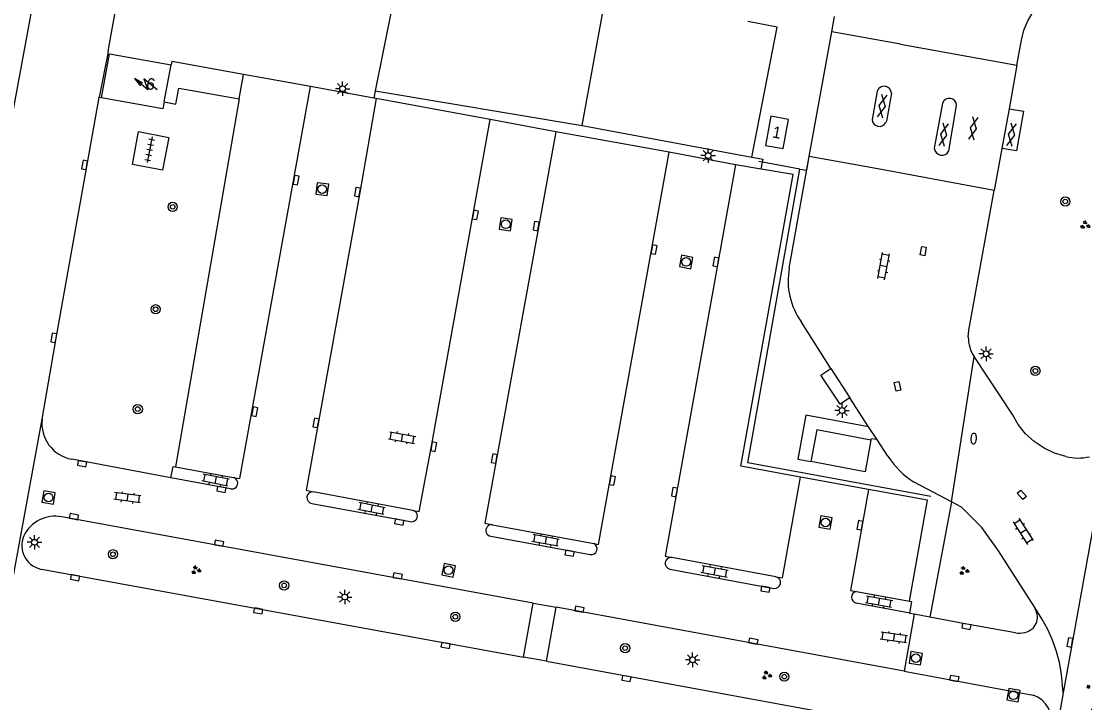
# Model space of a CAD drawing. Extents: x 130998 to 133001, y 398999 to 403002.
# Drawn here: x 132109.2 to 132201.3, y 399492.3 to 399551.3 of the extents above; entities that cross this region are included whole.
import ezdxf

# ---------------------------------------------------------------- set-up
doc = ezdxf.new("R2010")
doc.units = 0
for name, color, linetype in [('gg-afsc-erfafscheiding', 7, 'Continuous'), ('gg-afsc-hekwerk', 7, 'Continuous'), ('gg-anno-huisnummerreeks BGT', 7, 'Continuous'), ('gg-anno-openbare ruimte label', 7, 'Continuous'), ('gg-bbg-bijgebouw', 7, 'Continuous'), ('gg-bbg-hoofdgebouw', 7, 'Continuous'), ('gg-knt-verharding', 7, 'Continuous'), ('gg-knt-verharding nz', 7, 'Continuous'), ('gt-grn-groengrens', 7, 'Continuous'), ('gt-grn-vlakafsluiter', 7, 'Continuous'), ('gt-grn-weggrens', 7, 'Continuous'), ('gt-symb-boom', 7, 'Continuous'), ('gt-symb-brandkraan', 7, 'Continuous'), ('gt-symb-gesloten verharding', 7, 'Continuous'), ('gt-symb-groenvak', 7, 'Continuous'), ('gt-symb-klinker verharding', 7, 'Continuous'), ('gt-symb-kolk', 7, 'Continuous'), ('gt-symb-kolk center center', 7, 'Continuous'), ('gt-symb-lichtmast', 7, 'Continuous'), ('gt-symb-rioolschacht', 7, 'Continuous'), ('gt-symb-tegel verharding', 7, 'Continuous'), ('gt-symb-trafo symbool', 7, 'Continuous')]:
    doc.layers.add(name, color=color, linetype=linetype)

# ---------------------------------------------------------------- blocks, each defined once
blk = doc.blocks.new('gt0-BOOM')
at = {"layer": 'gt-symb-boom'}
for radius in [0.4, 0.2]:
    blk.add_circle((0, 0), radius, dxfattribs=at)
blk = doc.blocks.new('gt0-KOLK')
at = {"layer": 'gt-symb-kolk'}
blk.add_lwpolyline([(0, 0), (0.375, 0), (0.375, 0.4), (-0.375, 0.4), (-0.375, 0), (0, 0)], dxfattribs=at)
blk = doc.blocks.new('gt0-GRVAK')
at = {"layer": 'gt-symb-groenvak'}
for p, q in [((-0.11, 0.189), (-0.228, 0.24)), ((-0.182, 0.153), (0.088, 0.153)), ((-0.091, 0.211), (-0.156, 0.322)), ((-0.047, 0.214), (-0.047, 0.393)), ((-0.004, 0.211), (0.061, 0.322)), ((0.015, 0.189), (0.133, 0.24)), ((0.262, -0.052), (0.197, 0.059)), ((0.305, -0.049), (0.305, 0.13)), ((0.349, -0.052), (0.414, 0.059)), ((-0.245, -0.228), (-0.363, -0.177)), ((-0.318, -0.264), (-0.047, -0.264)), ((-0.226, -0.206), (-0.291, -0.095)), ((-0.183, -0.203), (-0.183, -0.024)), ((-0.139, -0.206), (-0.074, -0.095)), ((-0.12, -0.228), (-0.002, -0.177)), ((0.243, -0.074), (0.125, -0.023)), ((0.17, -0.11), (0.441, -0.11)), ((0.368, -0.074), (0.486, -0.023))]:
    blk.add_line(p, q, dxfattribs=at)
blk = doc.blocks.new('gt0-LMAST')
at = {"layer": 'gt-symb-lichtmast'}
for p, q in [((-0.182, 0.173), (-0.447, 0.438)), ((-0.005, 0.246), (-0.005, 0.621)), ((0.172, 0.173), (0.437, 0.438)), ((-0.255, -0.004), (-0.63, -0.004)), ((-0.182, -0.181), (-0.447, -0.446)), ((-0.005, -0.254), (-0.005, -0.629)), ((0.437, -0.446), (0.172, -0.181)), ((0.245, -0.004), (0.62, -0.004))]:
    blk.add_line(p, q, dxfattribs=at)
blk.add_circle((-0.005, -0.004), 0.25, dxfattribs=at)
blk = doc.blocks.new('gt0-RS')
at = {"layer": 'gt-symb-rioolschacht'}
blk.add_lwpolyline([(-0.5, -0.5), (0.5, -0.5), (0.5, 0.5), (-0.5, 0.5)], close=True, dxfattribs=at)
blk.add_circle((0, 0), 0.375, dxfattribs=at)
blk = doc.blocks.new('gt0-GESVH1')
at = {"layer": 'gt-symb-gesloten verharding'}
for p, q in [((-0.992, -0.261), (0.008, 0.239)), ((0.008, -0.261), (-0.992, 0.239)), ((0.008, 0.239), (1.008, -0.261)), ((1.008, 0.239), (0.008, -0.261))]:
    blk.add_line(p, q, dxfattribs=at)
blk = doc.blocks.new('gt0-TEG1')
at = {"layer": 'gt-symb-tegel verharding'}
for p, q in [((-1.125, 0), (1.125, 0)), ((-0.9, -0.25), (-0.9, 0.25)), ((-0.45, -0.25), (-0.45, 0.25)), ((0, -0.25), (0, 0.25)), ((0.45, -0.25), (0.45, 0.25)), ((0.9, -0.25), (0.9, 0.25))]:
    blk.add_line(p, q, dxfattribs=at)
blk = doc.blocks.new('gt0-HSP')
at = {"layer": 'gt-symb-trafo symbool'}
for points in [[(0.771, 0.746), (-0.529, -0.004), (0.471, -0.004), (-0.829, -0.754)], [(-0.217, -0.24), (-0.829, -0.754), (-0.077, -0.48)]]:
    blk.add_lwpolyline(points, dxfattribs=at)
blk = doc.blocks.new('gt0-KL1')
at = {"layer": 'gt-symb-klinker verharding'}
for p, q in [((-1.15, 0.3), (1.15, 0.3)), ((-1, -0.3), (-1, 0.3)), ((-0.5, 0.3), (-0.5, 0.45)), ((0, -0.3), (0, 0.3)), ((0.5, 0.3), (0.5, 0.45)), ((1, -0.3), (1, 0.3)), ((-1.15, -0.3), (1.15, -0.3)), ((-0.5, -0.45), (-0.5, -0.3)), ((0.5, -0.45), (0.5, -0.3))]:
    blk.add_line(p, q, dxfattribs=at)
blk = doc.blocks.new('gt0-KOLKCC')
at = {"layer": 'gt-symb-kolk center center'}
blk.add_lwpolyline([(-0.375, 0.2), (0.375, 0.2), (0.375, -0.2), (-0.375, -0.2)], close=True, dxfattribs=at)
blk = doc.blocks.new('gt0-BR')
at = {"layer": 'gt-symb-brandkraan'}
for centre, radius, start, end in [((-0.244, 0), 0.206, 107.56694, 252.43307), ((0.599, -2.664), 3, 106.89205, 107.56694), ((0, -0.691), 0.938, 73.10799, 106.89205), ((-0.599, -2.664), 3, 72.43309, 73.10799), ((0.244, 0), 0.206, 287.56695, 72.43309), ((0.599, 2.664), 3, 252.43307, 253.10797), ((0, 0.691), 0.938, 253.10797, 286.89206), ((-0.599, 2.664), 3, 286.89206, 287.56695)]:
    blk.add_arc(centre, radius, start, end, dxfattribs=at)

msp = doc.modelspace()

# ---------------------------------------------------------------- linework, layer by layer
at = {"layer": 'gg-afsc-erfafscheiding'}
msp.add_line((132157.773, 399542.297), (132172.48, 399539.565), dxfattribs=at)
msp.add_lwpolyline([(132172.48, 399539.565), (132174.679, 399550.803), (132172.135, 399551.301)], dxfattribs=at)
at = {"layer": 'gg-afsc-hekwerk'}
for p, q in [((132122.24, 399547.841), (132122.188, 399547.553)), ((132128.45, 399546.723), (132122.24, 399547.841)), ((132134.249, 399545.665), (132128.45, 399546.723)), ((132139.741, 399544.671), (132134.249, 399545.665)), ((132139.867, 399545.301), (132139.741, 399544.671)), ((132173.4, 399539.131), (132173.082, 399539.19)), ((132176.622, 399538.532), (132173.4, 399539.131))]:
    msp.add_line(p, q, dxfattribs=at)
msp.add_lwpolyline([(132187.97, 399510.197), (132172.118, 399513.098), (132176.622, 399538.532)], dxfattribs=at)
at = {"layer": 'gg-bbg-bijgebouw'}
for points in [[(132182.784, 399515.073), (132178.09, 399515.95), (132177.582, 399513.21)], [(132182.784, 399515.073), (132182.276, 399512.333), (132177.582, 399513.21)]]:
    msp.add_lwpolyline(points, dxfattribs=at)
at = {"layer": 'gg-bbg-hoofdgebouw'}
for p, q in [((132157.773, 399542.297), (132161.616, 399563.471)), ((132121.583, 399544.34), (132122.188, 399547.553)), ((132139.867, 399545.301), (132157.773, 399542.297)), ((132174.123, 399543.098), (132173.664, 399540.58))]:
    msp.add_line(p, q, dxfattribs=at)
for points in [[(132133.567, 399568.656), (132131.765, 399558.5), (132142.135, 399556.65), (132139.867, 399545.301)], [(132116.165, 399544.687), (132116.839, 399548.498), (132122.188, 399547.553)], [(132121.583, 399544.34), (132121.472, 399543.748), (132116.165, 399544.687)], [(132173.664, 399540.58), (132175.189, 399540.302), (132175.648, 399542.82), (132174.123, 399543.098)]]:
    msp.add_lwpolyline(points, dxfattribs=at)
at = {"layer": 'gg-knt-verharding'}
for p, q in [((132179.385, 399550.411), (132179.623, 399551.731)), ((132177.438, 399539.617), (132179.385, 399550.411)), ((132185.344, 399549.338), (132179.385, 399550.411)), ((132116.726, 399548.675), (132116.781, 399549.04)), ((132185.344, 399549.338), (132195.427, 399547.523)), ((132116.726, 399548.675), (132115.958, 399544.762)), ((132195.427, 399547.523), (132194.742, 399543.755)), ((132128.071, 399544.604), (132128.45, 399546.723)), ((132122.583, 399544.152), (132122.845, 399545.53)), ((132122.845, 399545.53), (132128.071, 399544.604)), ((132183.325, 399545.276), (132182.882, 399542.829)), ((132115.951, 399544.725), (132115.958, 399544.762)), ((132116.165, 399544.687), (132115.951, 399544.725)), ((132121.583, 399544.34), (132122.583, 399544.152)), ((132128.071, 399544.604), (132122.552, 399512.766)), ((132139.938, 399544.634), (132139.741, 399544.671)), ((132149.823, 399542.817), (132139.938, 399544.634)), ((132188.991, 399544.245), (132188.268, 399540.347)), ((132189.529, 399540.113), (132190.209, 399544.041)), ((132194.742, 399543.755), (132194.116, 399540.307)), ((132155.484, 399541.757), (132149.823, 399542.817)), ((132165.303, 399539.995), (132155.484, 399541.757)), ((132171.062, 399538.902), (132165.303, 399539.995)), ((132175.715, 399529.957), (132177.438, 399539.617)), ((132177.222, 399538.421), (132177.438, 399539.617)), ((132183.377, 399538.548), (132177.438, 399539.617)), ((132194.116, 399540.307), (132193.457, 399536.682)), ((132173.29, 399538.529), (132171.062, 399538.902)), ((132193.457, 399536.682), (132183.377, 399538.548)), ((132179.32, 399521.257), (132176.774, 399525.291)), ((132179.32, 399521.257), (132180.963, 399518.727)), ((132182.582, 399516.234), (132180.963, 399518.727)), ((132183.29, 399515.154), (132182.582, 399516.234)), ((132184.251, 399513.686), (132183.29, 399515.154)), ((132122.167, 399511.821), (132113.574, 399513.423)), ((132122.552, 399512.766), (132127.562, 399511.84)), ((132127.328, 399510.864), (132122.167, 399511.821)), ((132182.586, 399510.798), (132176.689, 399511.873)), ((132189.749, 399509.728), (132186.527, 399511.432)), ((132143.122, 399508.992), (132134.482, 399510.605)), ((132134.376, 399509.594), (132142.89, 399508.029)), ((132153.546, 399500.953), (132112.708, 399508.433)), ((132150.027, 399507.75), (132158.785, 399506.119)), ((132149.862, 399506.76), (132158.463, 399505.176)), ((132174.563, 399503.248), (132165.555, 399504.905)), ((132111.131, 399503.868), (132152.698, 399496.294)), ((132165.379, 399503.915), (132174.372, 399502.244)), ((132181.532, 399501.978), (132186.119, 399501.146)), ((132152.698, 399496.294), (132153.546, 399500.953)), ((132186.152, 399500.106), (132181.509, 399500.973)), ((132186.119, 399501.146), (132186.331, 399501.101)), ((132186.152, 399500.106), (132186.331, 399501.101)), ((132154.695, 399495.929), (132155.538, 399500.602)), ((132185.654, 399495.063), (132155.538, 399500.602)), ((132187.89, 399499.744), (132186.525, 399500)), ((132197.183, 399500), (132196.971, 399500.576)), ((132154.695, 399495.929), (132184.833, 399490.409)), ((132185.654, 399495.063), (132196.832, 399493.007))]:
    msp.add_line(p, q, dxfattribs=at)
for points in [[(132116.781, 399549.04), (132125.861, 399599.262), (132126.153, 399600.397), (132126.59, 399601.485), (132127.164, 399602.507), (132127.409, 399602.833)], [(132195.427, 399547.523), (132195.821, 399549.693), (132196.033, 399550.552), (132196.371, 399551.37), (132196.829, 399552.127), (132197.396, 399552.806), (132198.053, 399553.403), (132198.78, 399553.914)], [(132184.57, 399545.094), (132184.128, 399542.669), (132184.067, 399542.555)], [(132111.016, 399516.89), (132112.216, 399523.893), (132115.951, 399544.725)], [(132194.742, 399543.755), (132196.007, 399543.533), (132195.38, 399540.103), (132194.116, 399540.307)], [(132118.832, 399538.921), (132119.355, 399541.777), (132121.996, 399541.255), (132121.437, 399538.42), (132118.832, 399538.921)], [(132176.689, 399511.873), (132171.527, 399512.815), (132176.045, 399538.067), (132173.29, 399538.529)], [(132191.209, 399523.99), (132191.261, 399524.591), (132193.457, 399536.682)], [(132199.667, 399513.647), (132198.695, 399513.95), (132197.772, 399514.38), (132196.924, 399514.938), (132196.174, 399515.623), (132195.542, 399516.417), (132195.041, 399517.3), (132191.721, 399522.301)], [(132180.963, 399518.727), (132180.125, 399518.182), (132178.436, 399520.683), (132179.32, 399521.257)], [(132182.582, 399516.234), (132177.161, 399517.243), (132176.448, 399513.422), (132177.582, 399513.21)], [(132182.784, 399515.073), (132182.834, 399515.219), (132183.29, 399515.154)], [(132122.167, 399511.821), (132122.362, 399512.801), (132122.552, 399512.766)], [(132186.119, 399501.146), (132187.682, 399509.874), (132182.586, 399510.798)], [(132196.971, 399500.576), (132193.841, 399505.48), (132192.391, 399507.501), (132190.641, 399509.26), (132189.749, 399509.728)], [(132186.525, 399500), (132186.146, 399500.071), (132186.152, 399500.106)], [(132195.308, 399498.402), (132191.089, 399499.144), (132187.89, 399499.744)]]:
    msp.add_lwpolyline(points, dxfattribs=at)
for centre, radius, start, end in [((132183.928, 399545.055), 0.643, 3.4786, 159.88768), ((132189.579, 399544.02), 0.63, 1.95134, 159.03248), ((132183.511, 399542.85), 0.629, 181.92917, 332.03216), ((132188.928, 399540.389), 0.661, 183.66038, 335.31437), ((132181.668, 399528.855), 6.054, 169.51225, 216.06231), ((132194.376, 399524.028), 3.167, 180.68478, 213.04332), ((132114.127, 399516.508), 3.134, 173.00034, 259.84049), ((132190.559, 399517.78), 7.52, 212.98191, 237.5746), ((132200.718, 399518.07), 4.546, 256.63325, 282.46448), ((132127.451, 399511.351), 0.502, 255.82896, 77.20622), ((132134.449, 399510.097), 0.509, 86.27354, 261.75565), ((132112.146, 399505.473), 3.012, 79.2464, 154.23306), ((132143.015, 399508.508), 0.495, 255.44013, 77.46941), ((132149.938, 399507.256), 0.502, 79.83737, 261.23798), ((132111.35, 399505.947), 2.091, 156.4472, 263.99477), ((132158.562, 399505.669), 0.503, 258.69477, 63.59891), ((132165.469, 399504.41), 0.503, 80.14423, 259.69457), ((132174.449, 399502.75), 0.511, 261.37927, 77.07835), ((132181.614, 399501.473), 0.511, 99.24644, 258.13152), ((132195.761, 399499.761), 1.442, 317.60852, 9.54069), ((132195.65, 399500.231), 1.86, 259.4024, 309.20233), ((132196.05, 399490.766), 2.374, 345.10972, 70.76789)]:
    msp.add_arc(centre, radius, start, end, dxfattribs=at)
at = {"layer": 'gg-knt-verharding nz'}
for p, q in [((132110.589, 399555.075), (132107.825, 399539.947)), ((132203.385, 399515.204), (132199.442, 399493.213)), ((132199.442, 399493.213), (132198.877, 399490.061))]:
    msp.add_line(p, q, dxfattribs=at)
for points in [[(132127.562, 399511.84), (132128.144, 399511.737), (132134.249, 399545.665)], [(132139.938, 399544.634), (132138.512, 399536.507), (132133.877, 399510.743), (132134.482, 399510.605)], [(132143.122, 399508.992), (132143.674, 399508.894), (132144.732, 399514.543), (132149.823, 399542.817)], [(132155.484, 399541.757), (132149.347, 399507.885), (132150.027, 399507.75)], [(132158.785, 399506.119), (132159.181, 399506.048), (132165.303, 399539.995)], [(132171.062, 399538.902), (132164.967, 399505.033), (132165.555, 399504.905)], [(132174.563, 399503.248), (132175.133, 399503.147), (132176.689, 399511.873)], [(132182.586, 399510.798), (132181.012, 399502.06), (132181.532, 399501.978)]]:
    msp.add_lwpolyline(points, dxfattribs=at)
at = {"layer": 'gt-grn-groengrens'}
msp.add_line((132189.749, 399509.728), (132187.89, 399499.744), dxfattribs=at)
at = {"layer": 'gt-grn-vlakafsluiter'}
for p, q in [((132172.48, 399539.565), (132173.446, 399539.385)), ((132173.29, 399538.529), (132173.4, 399539.131)), ((132173.4, 399539.131), (132173.446, 399539.385)), ((132176.622, 399538.532), (132177.222, 399538.421))]:
    msp.add_line(p, q, dxfattribs=at)
at = {"layer": 'gt-grn-weggrens'}
for p, q in [((132189.749, 399509.728), (132191.721, 399522.301)), ((132105.982, 399489.503), (132111.016, 399516.89)), ((132153.546, 399500.953), (132155.538, 399500.602)), ((132186.525, 399500), (132185.654, 399495.063)), ((132154.695, 399495.929), (132152.698, 399496.294))]:
    msp.add_line(p, q, dxfattribs=at)
msp.add_lwpolyline([(132199.442, 399493.213), (132199.28, 399494.824), (132199.101, 399495.817), (132198.844, 399496.793), (132198.51, 399497.746), (132198.101, 399498.669), (132197.595, 399499.598), (132196.971, 399500.576)], dxfattribs=at)

# ---------------------------------------------------------------- block references
at = {"layer": 'gt-symb-boom'}
for p in [(132199.618, 399535.719), (132122.319, 399535.26), (132120.843, 399526.395), (132197.027, 399521.062), (132119.294, 399517.754), (132117.15, 399505.194), (132131.971, 399502.497), (132146.793, 399499.786), (132161.5, 399497.069), (132175.288, 399494.603)]:
    msp.add_blockref('gt0-BOOM', p, dxfattribs=at)
at = {"layer": 'gt-symb-brandkraan', "rotation": -94.64472160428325}
msp.add_blockref('gt0-BR', (132191.68, 399515.204), dxfattribs=at)
at = {"layer": 'gt-symb-gesloten verharding'}
for p, rotation in [((132183.746, 399543.97), 79.69002960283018), ((132189.072, 399541.496), 79.6900296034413), ((132191.642, 399542.046), 79.69002960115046), ((132194.945, 399541.496), 79.6900296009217)]:
    msp.add_blockref('gt0-GESVH1', p, dxfattribs=dict(at, rotation=rotation))
at = {"layer": 'gt-symb-groenvak', "rotation": -10.30997039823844}
msp.add_blockref('gt0-GRVAK', (132201.333, 399533.672), dxfattribs=at)
at = {"layer": 'gt-symb-groenvak'}
for p in [(132124.328, 399503.818), (132190.84, 399503.769), (132173.755, 399494.712)]:
    msp.add_blockref('gt0-GRVAK', p, dxfattribs=at)
at = {"layer": 'gt-symb-klinker verharding'}
for p, rotation in [((132183.881, 399530.128), 79.69002960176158), ((132142.193, 399515.284), -10.25359802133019), ((132126.025, 399511.609), 168.81367070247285), ((132118.394, 399510.099), 172.70443985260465), ((132139.537, 399509.146), 168.70129979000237), ((132195.965, 399507.181), -57.454106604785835), ((132154.615, 399506.393), 169.6336773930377), ((132169.249, 399503.696), 169.28535610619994), ((132183.493, 399501.102), -10.074332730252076), ((132184.768, 399497.989), 171.89420641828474)]:
    msp.add_blockref('gt0-KL1', p, dxfattribs=dict(at, rotation=rotation))
at = {"layer": 'gt-symb-kolk'}
for p, rotation in [((132114.883, 399538.848), 79.85920685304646), ((132132.807, 399537.604), -100.1407931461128), ((132138.512, 399536.507), 80.03848340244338), ((132148.333, 399534.591), -100.19720557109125), ((132153.984, 399533.558), 79.63367739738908), ((132163.806, 399531.596), -100.25359802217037), ((132169.559, 399530.457), 79.92566727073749), ((132112.216, 399523.893), 80.27403432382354), ((132129.217, 399517.57), -100.4330247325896), ((132134.926, 399516.529), 79.80279442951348), ((132144.732, 399514.543), -100.60205829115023), ((132150.357, 399513.433), 79.80279442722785), ((132114.512, 399513.225), 169.6336774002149), ((132160.191, 399511.608), -100.30997039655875), ((132126.573, 399511.002), 169.63367739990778), ((132165.97, 399510.544), 79.80279442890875), ((132113.729, 399508.25), -10.366322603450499), ((132141.971, 399508.187), 169.51061019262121), ((132182.025, 399507.673), 79.80279442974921), ((132126.306, 399505.954), -10.36632260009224), ((132156.72, 399505.479), 169.39794170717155), ((132113.9, 399503.365), 169.69002960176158), ((132141.765, 399503.126), -10.433024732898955), ((132173.689, 399502.366), 169.45426563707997), ((132129.759, 399500.488), 169.74640197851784), ((132157.503, 399500.242), -10.422654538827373), ((132191.089, 399499.144), 170.03848340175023), ((132145.988, 399497.497), 169.56697527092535), ((132172.565, 399497.476), -10.36632260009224), ((132200.211, 399497.531), 79.51061018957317), ((132161.65, 399494.634), 169.45426563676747), ((132189.971, 399494.246), -10.25359802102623)]:
    msp.add_blockref('gt0-KOLK', p, dxfattribs=dict(at, rotation=rotation))
at = {"layer": 'gt-symb-kolk center center'}
for p, rotation in [((132187.318, 399531.431), 79.69002960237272), ((132185.082, 399519.728), -76.99249520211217), ((132195.853, 399510.34), -49.013466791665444)]:
    msp.add_blockref('gt0-KOLKCC', p, dxfattribs=dict(at, rotation=rotation))
at = {"layer": 'gt-symb-lichtmast'}
for p in [(132137.038, 399545.482), (132168.695, 399539.693), (132180.289, 399517.643), (132110.36, 399506.231), (132137.224, 399501.499), (132167.345, 399496.063)]:
    msp.add_blockref('gt0-LMAST', p, dxfattribs=at)
at = {"layer": 'gt-symb-lichtmast', "rotation": -90.00000000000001}
msp.add_blockref('gt0-LMAST', (132192.762, 399522.535), dxfattribs=at)
at = {"layer": 'gt-symb-rioolschacht'}
for p, rotation in [((132135.272, 399536.793), 82.99574075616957), ((132151.159, 399533.747), -98.80280445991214), ((132166.786, 399530.488), -101.00666417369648), ((132111.576, 399510.105), 170.55652508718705), ((132178.851, 399507.94), -99.66950525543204), ((132146.211, 399503.805), 169.04956573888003), ((132186.667, 399496.196), 80.73547601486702), ((132195.123, 399492.989), -100.01793447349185)]:
    msp.add_blockref('gt0-RS', p, dxfattribs=dict(at, rotation=rotation))
at = {"layer": 'gt-symb-tegel verharding', "rotation": -101.07387115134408}
msp.add_blockref('gt0-TEG1', (132120.334, 399540.2), dxfattribs=at)
at = {"layer": 'gt-symb-trafo symbool', "rotation": -69.87983420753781}
msp.add_blockref('gt0-HSP', (132120.008, 399545.839), dxfattribs=at)

# ---------------------------------------------------------------- texts
at = {"layer": 'gg-anno-huisnummerreeks BGT'}
for s, rotation, p in [('6', 350, (132119.971, 399545.471)), ('1', 349.7, (132174.184, 399541.277))]:
    msp.add_text(s, height=1, rotation=rotation, dxfattribs=at).set_placement(p)
at = {"layer": 'gg-anno-openbare ruimte label'}
msp.add_text('Henri Blomjousstraat', height=2.5, rotation=79.7, dxfattribs=at).set_placement((132201.04, 399476.65))

doc.saveas('drawing.dxf')
